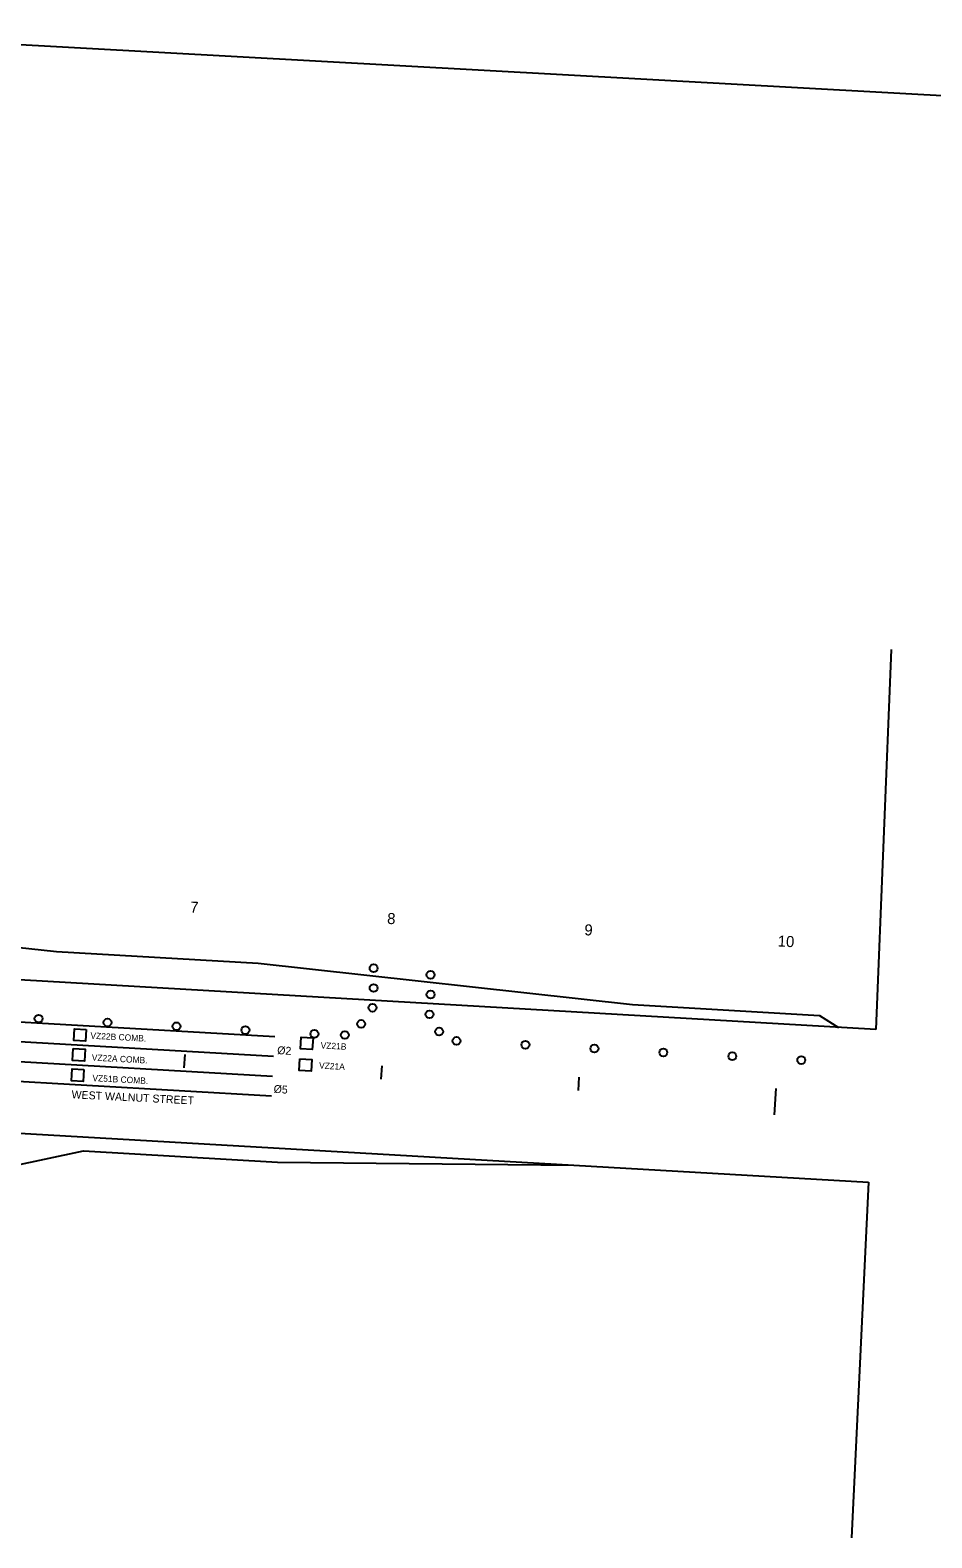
# Model space of a CAD drawing. Extents: x 0 to 1361828, y 0 to 1470398.
# Drawn here: x 686377 to 686834, y 734596 to 735359 of the extents above; entities that cross this region are included whole.
import ezdxf

# ---------------------------------------------------------------- set-up
doc = ezdxf.new("R2010")
doc.units = 0
for name, color, linetype in [('$', 7, 'Continuous'), ('BASE', 7, 'Continuous'), ('border All Plan 20-40 - Level 1', 7, 'Continuous'), ('MOT Stage 1', 7, 'Continuous'), ('MOT Stage 1 Lanes', 7, 'Continuous'), ('R_Horz Alg Station', 7, 'Continuous'), ('RW-EX', 7, 'Continuous'), ('RW-PR', 7, 'Continuous'), ('SIGNAL-PR$', 7, 'Continuous'), ('TITEXT', 7, 'Continuous'), ('Video-Zones-pr', 7, 'Continuous')]:
    doc.layers.add(name, color=color, linetype=linetype)

# ---------------------------------------------------------------- blocks, each defined once
blk = doc.blocks.new('BAREL_1786')
at = {"layer": 'MOT Stage 1'}
blk.add_circle((0, 0), 2.88, dxfattribs=at)
blk = doc.blocks.new('BAREL_1787')
at = {"layer": 'MOT Stage 1'}
blk.add_circle((0, 0), 2.88, dxfattribs=at)
blk = doc.blocks.new('BAREL_1788')
at = {"layer": 'MOT Stage 1'}
blk.add_circle((0, 0), 2.88, dxfattribs=at)
blk = doc.blocks.new('BAREL_1789')
at = {"layer": 'MOT Stage 1'}
blk.add_circle((0, 0), 2.88, dxfattribs=at)
blk = doc.blocks.new('BAREL_1823')
at = {"layer": 'MOT Stage 1'}
blk.add_circle((0, 0), 2.88, dxfattribs=at)
blk = doc.blocks.new('BAREL_1824')
at = {"layer": 'MOT Stage 1'}
blk.add_circle((0, 0), 2.88, dxfattribs=at)
blk = doc.blocks.new('BAREL_1825')
at = {"layer": 'MOT Stage 1'}
blk.add_circle((0, 0), 2.88, dxfattribs=at)
blk = doc.blocks.new('BAREL_1826')
at = {"layer": 'MOT Stage 1'}
blk.add_circle((0, 0), 2.88, dxfattribs=at)
blk = doc.blocks.new('BAREL_1827')
at = {"layer": 'MOT Stage 1'}
blk.add_circle((0, 0), 2.88, dxfattribs=at)
blk = doc.blocks.new('BAREL_1828')
at = {"layer": 'MOT Stage 1'}
blk.add_circle((0, 0), 2.88, dxfattribs=at)
blk = doc.blocks.new('BAREL_1829')
at = {"layer": 'MOT Stage 1'}
blk.add_circle((0, 0), 2.88, dxfattribs=at)
blk = doc.blocks.new('BAREL_1830')
at = {"layer": 'MOT Stage 1'}
blk.add_circle((0, 0), 2.88, dxfattribs=at)
blk = doc.blocks.new('BAREL_1831')
at = {"layer": 'MOT Stage 1'}
blk.add_circle((0, 0), 2.88, dxfattribs=at)
blk = doc.blocks.new('BAREL_1832')
at = {"layer": 'MOT Stage 1'}
blk.add_circle((0, 0), 2.88, dxfattribs=at)
blk = doc.blocks.new('BAREL_1833')
at = {"layer": 'MOT Stage 1'}
blk.add_circle((0, 0), 2.88, dxfattribs=at)
blk = doc.blocks.new('BAREL_1834')
at = {"layer": 'MOT Stage 1'}
blk.add_circle((0, 0), 2.88, dxfattribs=at)
blk = doc.blocks.new('BAREL_1835')
at = {"layer": 'MOT Stage 1'}
blk.add_circle((0, 0), 2.88, dxfattribs=at)
blk = doc.blocks.new('BAREL_1836')
at = {"layer": 'MOT Stage 1'}
blk.add_circle((0, 0), 2.88, dxfattribs=at)
blk = doc.blocks.new('BAREL_1837')
at = {"layer": 'MOT Stage 1'}
blk.add_circle((0, 0), 2.88, dxfattribs=at)
blk = doc.blocks.new('BAREL_1838')
at = {"layer": 'MOT Stage 1'}
blk.add_circle((0, 0), 2.88, dxfattribs=at)

msp = doc.modelspace()

# ---------------------------------------------------------------- linework, layer by layer
at = {"layer": 'border All Plan 20-40 - Level 1'}
msp.add_line((685446.82, 735403.36), (687025.3, 735315.9), dxfattribs=at)
at = {"layer": 'MOT Stage 1 Lanes'}
for p, q in [((686314.76, 734860.32), (686501.05, 734849.6)), ((686314.19, 734850.33), (686500.48, 734839.61)), ((686313.61, 734840.33), (686499.9, 734829.61))]:
    msp.add_line(p, q, dxfattribs=at)
msp.add_lwpolyline([(686314.02, 734864.85), (686312.04, 734830.43), (686499.33, 734819.65)], dxfattribs=at)
at = {"layer": 'R_Horz Alg Station'}
for points in [[(686455.45, 734840.47), (686455.07, 734833.81)], [(686555.29, 734834.72), (686554.9, 734828.07)], [(686655.12, 734828.97), (686654.74, 734822.32)], [(686754.96, 734823.23), (686754.19, 734809.91)]]:
    msp.add_lwpolyline(points, dxfattribs=at)
at = {"layer": 'RW-EX'}
for p, q in [((686813.51, 735045.58), (686805.63, 734853.17)), ((686805.63, 734853.17), (686309.65, 734882.01)), ((686492.64, 734886.74), (686682.28, 734865.81)), ((686316.03, 734803.86), (686801.87, 734775.88)), ((686801.87, 734775.88), (686793.39, 734595.69))]:
    msp.add_line(p, q, dxfattribs=at)
at = {"layer": 'RW-PR'}
for points in [[(686343.56, 734897.83), (686390.39, 734892.63), (686492.64, 734886.74), (686682.28, 734865.81), (686777.13, 734860.35), (686786.79, 734854.26)], [(686331.18, 734751.21), (686367.05, 734783.79), (686404.18, 734791.67), (686502.4, 734786.01), (686652.56, 734784.48)]]:
    msp.add_lwpolyline(points, dxfattribs=at)
at = {"layer": 'Video-Zones-pr'}
for points in [[(686405.5, 734853.21), (686405.16, 734847.22), (686399.17, 734847.56), (686399.51, 734853.55)], [(686398.94, 734843.53), (686404.93, 734843.19), (686404.58, 734837.2), (686398.59, 734837.54)], [(686520.45, 734848.97), (686520.1, 734842.98), (686514.11, 734843.33), (686514.46, 734849.32)], [(686513.83, 734838.33), (686519.82, 734837.99), (686519.47, 734832), (686513.48, 734832.34)], [(686404.33, 734832.88), (686403.99, 734826.89), (686398, 734827.23), (686398.34, 734833.22)]]:
    msp.add_lwpolyline(points, close=True, dxfattribs=at)

# ---------------------------------------------------------------- block references
at = {"layer": '$', "xscale": 0.6945420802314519, "yscale": 0.6945420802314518, "rotation": 87.04179557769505}
msp.add_blockref('BAREL_1786', (686551.16, 734884.19), dxfattribs=at)
at = {"layer": 'MOT Stage 1'}
for name, p, xscale, yscale, rotation in [('BAREL_1788', (686580.04, 734880.86), 0.6945420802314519, 0.6945420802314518, 87.04179557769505), ('BAREL_1787', (686551.16, 734874.19), 0.6945420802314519, 0.6945420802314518, 87.04179557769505), ('BAREL_1823', (686550.6, 734864.21), 0.6945420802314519, 0.6945420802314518, 87.04179557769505), ('BAREL_1789', (686580.04, 734870.86), 0.6945420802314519, 0.6945420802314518, 87.04179557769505), ('BAREL_1834', (686381.36, 734858.68), 0.6945420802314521, 0.6945420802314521, 99.12424692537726), ('BAREL_1835', (686416.31, 734856.74), 0.6945420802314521, 0.6945420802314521, 99.12424692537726), ('BAREL_1824', (686544.86, 734856.02), 0.6945420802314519, 0.6945420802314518, 87.04179557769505), ('BAREL_1826', (686579.49, 734860.87), 0.6945420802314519, 0.6945420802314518, 87.04179557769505), ('BAREL_1836', (686451.26, 734854.8), 0.6945420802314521, 0.6945420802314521, 99.12424692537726), ('BAREL_1837', (686486.2, 734852.87), 0.6945420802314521, 0.6945420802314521, 99.12424692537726), ('BAREL_1838', (686521.15, 734850.93), 0.6945420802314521, 0.6945420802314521, 99.12424692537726), ('BAREL_1825', (686536.59, 734850.39), 0.6945420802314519, 0.6945420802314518, 87.04179557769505), ('BAREL_1827', (686584.36, 734852.14), 0.6945420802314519, 0.6945420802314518, 87.04179557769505), ('BAREL_1828', (686593.15, 734847.39), 0.6945420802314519, 0.6945420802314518, 87.04179557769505), ('BAREL_1829', (686628.1, 734845.45), 0.6945420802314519, 0.6945420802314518, 87.04179557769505), ('BAREL_1830', (686663.05, 734843.51), 0.6945420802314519, 0.6945420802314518, 87.04179557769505), ('BAREL_1831', (686697.99, 734841.58), 0.6945420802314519, 0.6945420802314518, 87.04179557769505), ('BAREL_1832', (686732.94, 734839.64), 0.6945420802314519, 0.6945420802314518, 87.04179557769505), ('BAREL_1833', (686767.89, 734837.7), 0.6945420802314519, 0.6945420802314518, 87.04179557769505)]:
    msp.add_blockref(name, p, dxfattribs=dict(at, xscale=xscale, yscale=yscale, rotation=rotation))

# ---------------------------------------------------------------- texts
at = {"layer": '$'}
for s, p in [('7', (686458.09, 734912.43)), ('8', (686557.92, 734906.68)), ('9', (686657.87, 734900.93)), ('10', (686755.89, 734895.27))]:
    msp.add_text(s, height=5.6, rotation=357.04154, dxfattribs=at).set_placement(p)
at = {"layer": 'BASE'}
msp.add_text('WEST WALNUT STREET', height=4, rotation=357.12141, dxfattribs=at).set_placement((686398.03, 734818.33))
at = {"layer": 'SIGNAL-PR$'}
for s, p in [('VZ22B COMB.', (686407.59, 734848.52)), ('VZ21B', (686524.24, 734843.59)), ('VZ22A COMB.', (686408.26, 734837.46)), ('VZ21A', (686523.45, 734833.39)), ('VZ51B COMB.', (686408.6, 734827.05))]:
    msp.add_text(s, height=3.2, rotation=356.95165, dxfattribs=at).set_placement(p)
at = {"layer": 'TITEXT'}
for s, p in [('%%C2', (686502.21, 734840.77)), ('%%C5', (686500.38, 734821.13))]:
    msp.add_text(s, height=4, rotation=356.2723, dxfattribs=at).set_placement(p)

doc.saveas('drawing.dxf')
